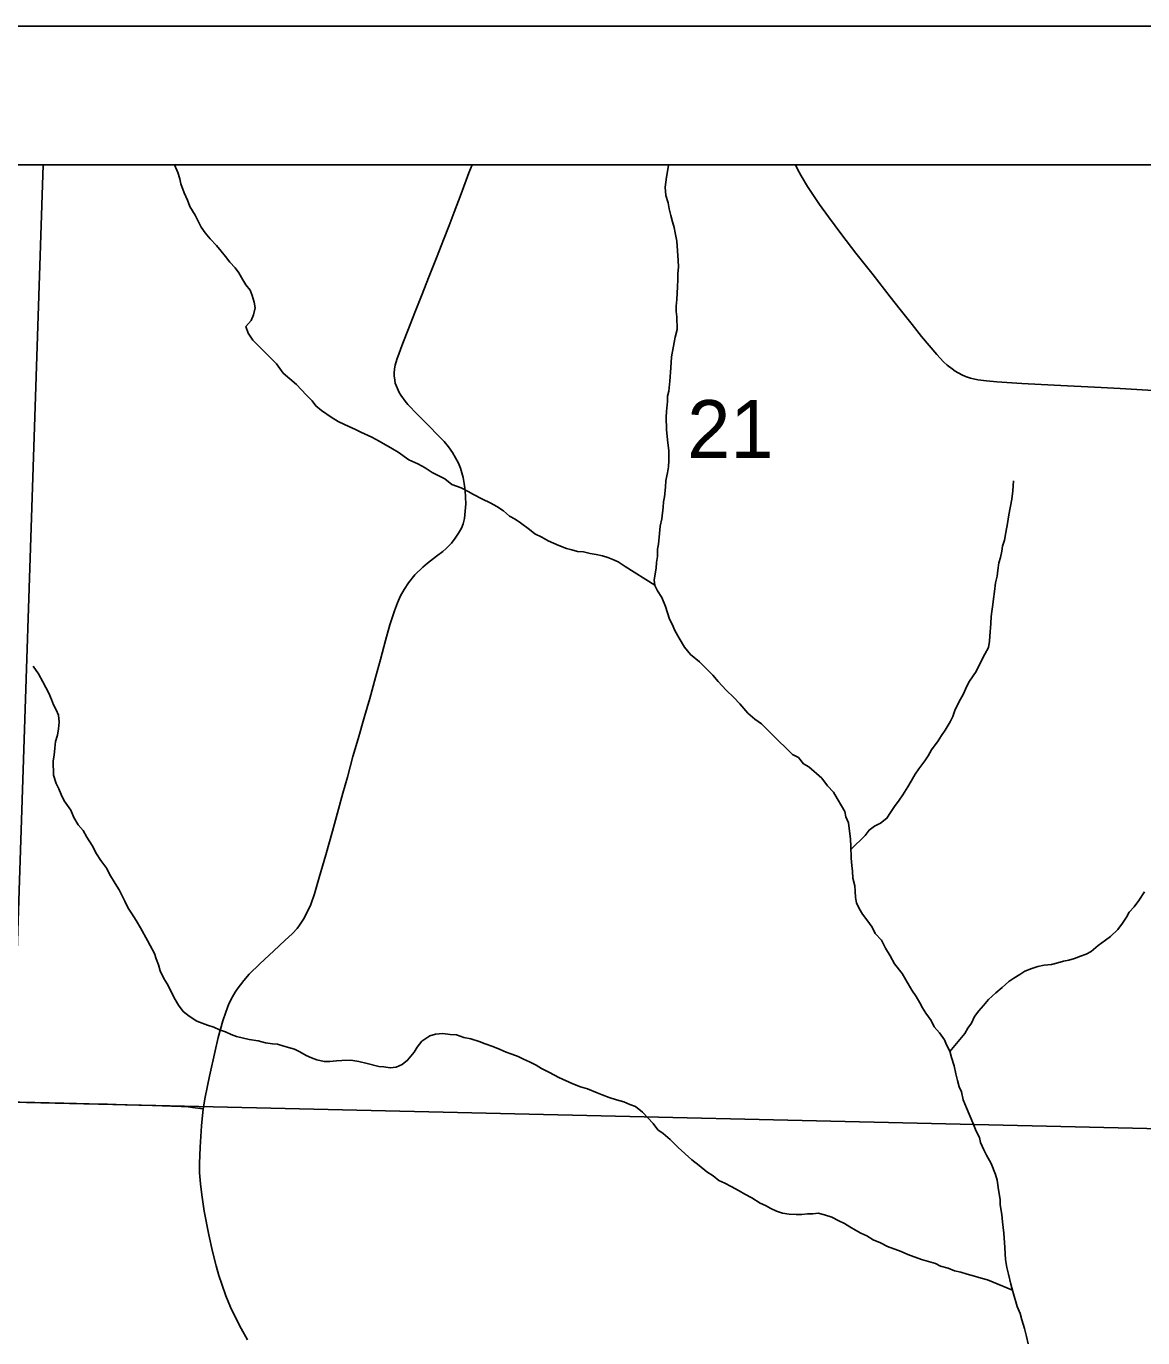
# Model space of a CAD drawing. Extents: x -7.9 to 76.1, y 0 to 22.
# Drawn here: x 7.388 to 8.194, y 20.053 to 21 of the extents above; entities that cross this region are included whole.
import ezdxf

# ---------------------------------------------------------------- set-up
doc = ezdxf.new("R2010")
doc.units = 0
for name, color, linetype in [('GM_X_County_Road', 7, 'Continuous'), ('GM_X_Minor_River', 7, 'Continuous'), ('GM_X_Section', 7, 'Continuous'), ('GM_X_Section_Text', 7, 'Continuous'), ('GM_X_Township_Road', 7, 'Continuous'), ('SC_Scratch1', 7, 'Continuous'), ('SH_Data', 7, 'Continuous')]:
    doc.layers.add(name, color=color, linetype=linetype)

msp = doc.modelspace()

# ---------------------------------------------------------------- linework, layer by layer
at = {"layer": 'GM_X_County_Road'}
for points in [[(7.54723, 20.05132), (7.54263, 20.05954), (7.53885, 20.06693), (7.53499, 20.07499), (7.53153, 20.08304), (7.52865, 20.09143), (7.5266, 20.09776), (7.52471, 20.10483), (7.522, 20.11511), (7.51928, 20.12719), (7.51592, 20.14437), (7.51419, 20.15596), (7.51329, 20.16402), (7.51271, 20.17191), (7.51263, 20.17865), (7.51312, 20.19049), (7.51411, 20.20578), (7.51526, 20.21819), (7.51666, 20.22649), (7.51986, 20.24178), (7.52397, 20.26011), (7.52619, 20.26956), (7.5294, 20.28165), (7.53153, 20.28789), (7.5339, 20.29391), (7.53655, 20.29908), (7.53844, 20.30241), (7.53975, 20.30446), (7.54462, 20.31089), (7.54847, 20.31543), (7.55619, 20.32299), (7.56619, 20.33218), (7.57428, 20.33961), (7.57987, 20.34486), (7.58307, 20.34847), (7.58488, 20.35078), (7.58776, 20.35522), (7.59039, 20.36023), (7.59294, 20.36582), (7.59573, 20.37339), (7.59915, 20.38522), (7.60378, 20.40161), (7.60861, 20.41869), (7.61229, 20.43192), (7.61621, 20.44605), (7.61938, 20.45759), (7.62346, 20.47267), (7.62731, 20.48545), (7.63188, 20.50158), (7.63555, 20.5145), (7.63969, 20.5297), (7.64324, 20.54274), (7.64696, 20.55643), (7.65003, 20.56768), (7.65344, 20.57782), (7.6555, 20.58358), (7.65779, 20.58859), (7.66035, 20.59328), (7.66347, 20.59812), (7.66809, 20.60383), (7.67393, 20.60929), (7.67728, 20.61227), (7.68385, 20.61719), (7.68844, 20.62077), (7.69078, 20.62283), (7.69456, 20.62677), (7.69716, 20.63027), (7.69974, 20.63383), (7.7018, 20.63747), (7.70297, 20.64061), (7.70401, 20.64456), (7.70457, 20.64983), (7.70488, 20.65507), (7.7045, 20.66459), (7.70375, 20.66988), (7.70297, 20.67417), (7.70109, 20.68093), (7.69964, 20.68452), (7.69759, 20.68835), (7.69528, 20.69217), (7.69232, 20.69627), (7.68936, 20.70006), (7.68517, 20.70425), (7.67799, 20.71154), (7.66996, 20.7197), (7.66306, 20.72691), (7.66112, 20.72926), (7.65808, 20.73345), (7.65691, 20.73543), (7.65525, 20.73877), (7.65399, 20.74213), (7.65356, 20.74441), (7.65325, 20.74754), (7.65322, 20.74933), (7.65344, 20.75256), (7.65389, 20.75511), (7.65501, 20.75923), (7.6594, 20.77114), (7.66344, 20.78136), (7.66813, 20.79322), (7.67289, 20.80526), (7.67854, 20.81939), (7.68386, 20.83272), (7.68885, 20.8457), (7.69281, 20.85599), (7.69658, 20.86578), (7.7015, 20.87897), (7.70717, 20.89418), (7.70946, 20.9)], [(8.2054, 20.73666), (8.17732, 20.73839), (8.16373, 20.73916), (8.1298, 20.74077), (8.10638, 20.74203), (8.08827, 20.74314), (8.08085, 20.74386), (8.07455, 20.7447), (8.06942, 20.74583), (8.06564, 20.74698), (8.06319, 20.7482), (8.05826, 20.751), (8.05611, 20.75251), (8.05257, 20.75528), (8.04993, 20.7576), (8.04503, 20.76293), (8.03408, 20.77595), (8.02725, 20.78468), (8.01869, 20.79539), (8.01127, 20.80467), (7.99904, 20.82041), (7.98659, 20.83616), (7.97636, 20.84945), (7.9668, 20.86242), (7.96036, 20.87114), (7.95165, 20.88424), (7.9471, 20.8919), (7.94448, 20.89673), (7.94298, 20.9)]]:
    msp.add_lwpolyline(points, dxfattribs=at)
at = {"layer": 'GM_X_Minor_River'}
for points in [[(7.4945, 20.9), (7.49688, 20.89444), (7.49845, 20.88991), (7.49926, 20.88612), (7.50162, 20.8797), (7.50397, 20.87442), (7.50555, 20.86989), (7.50943, 20.8635), (7.51137, 20.85973), (7.51371, 20.85483), (7.5168, 20.8507), (7.52027, 20.84657), (7.52488, 20.8417), (7.52835, 20.83758), (7.53144, 20.83382), (7.53452, 20.82969), (7.53837, 20.82557), (7.54108, 20.82181), (7.5438, 20.81692), (7.54612, 20.81316), (7.54921, 20.80941), (7.55077, 20.80563), (7.55198, 20.80072), (7.55279, 20.79655), (7.55172, 20.79161), (7.54988, 20.78741), (7.54615, 20.78318), (7.54773, 20.77827), (7.55121, 20.77339), (7.55467, 20.76964), (7.55889, 20.76553), (7.56274, 20.76178), (7.56812, 20.75617), (7.57314, 20.74941), (7.57775, 20.7453), (7.58273, 20.74119), (7.58966, 20.7337), (7.59388, 20.72958), (7.59659, 20.72583), (7.6008, 20.72247), (7.60769, 20.71763), (7.61266, 20.71466), (7.61724, 20.71245), (7.62525, 20.70877), (7.62907, 20.70692), (7.63708, 20.70324), (7.64243, 20.70028), (7.65198, 20.69472), (7.65618, 20.6925), (7.66384, 20.68691), (7.67033, 20.68397), (7.67568, 20.68101), (7.68065, 20.67766), (7.68981, 20.67323), (7.6948, 20.66913), (7.70165, 20.66657), (7.70662, 20.66398), (7.71044, 20.66176), (7.71655, 20.6588), (7.72304, 20.65548), (7.72724, 20.65326), (7.73221, 20.64992), (7.73643, 20.64618), (7.74063, 20.64396), (7.74446, 20.64136), (7.75097, 20.63652), (7.7548, 20.63353), (7.75977, 20.63095), (7.76435, 20.62835), (7.77198, 20.62504), (7.7777, 20.62285), (7.7815, 20.62176)], [(7.85139, 20.9), (7.85134, 20.89933), (7.84994, 20.89096), (7.8489, 20.88374), (7.84936, 20.87768), (7.85095, 20.87239), (7.85176, 20.86823), (7.85296, 20.86331), (7.85416, 20.85877), (7.85535, 20.85462), (7.85616, 20.85083), (7.85738, 20.84478), (7.85833, 20.83075), (7.85839, 20.8262), (7.85808, 20.82126), (7.85813, 20.81709), (7.85783, 20.81177), (7.85719, 20.80266), (7.85688, 20.79772), (7.85693, 20.79393), (7.85736, 20.79014), (7.85748, 20.78104), (7.85604, 20.77533), (7.85533, 20.77152), (7.85357, 20.76125), (7.85292, 20.75328), (7.85229, 20.74378), (7.85163, 20.73656), (7.85054, 20.73275), (7.85059, 20.72896), (7.84993, 20.72174), (7.84961, 20.71756), (7.84973, 20.70884), (7.85059, 20.70126), (7.85145, 20.69331), (7.85154, 20.68648), (7.85122, 20.68192), (7.85053, 20.67736), (7.84946, 20.67203), (7.84915, 20.66709), (7.84848, 20.66025), (7.84777, 20.65645), (7.84745, 20.65265), (7.84642, 20.64429), (7.84535, 20.63896), (7.84467, 20.63364), (7.84401, 20.62604), (7.8433, 20.62224), (7.84337, 20.61693), (7.84267, 20.61275), (7.84235, 20.60857), (7.84095, 20.6002), (7.84138, 20.59603), (7.84333, 20.59227), (7.84642, 20.58738), (7.84916, 20.58097), (7.85194, 20.5719), (7.85389, 20.56813), (7.85584, 20.5636), (7.85895, 20.55796), (7.86283, 20.55156)], [(8.10048, 20.67175), (8.09982, 20.66453), (8.09914, 20.65845), (8.09702, 20.64704), (8.09596, 20.64096), (8.09491, 20.63449), (8.09385, 20.62879), (8.09239, 20.62459), (8.09206, 20.62079), (8.09098, 20.61622), (8.0899, 20.61241), (8.08921, 20.60709), (8.08851, 20.60291), (8.08744, 20.59796), (8.08676, 20.59188), (8.08607, 20.58656), (8.08537, 20.58238), (8.08468, 20.57743), (8.08435, 20.57363), (8.08404, 20.5687), (8.0834, 20.55958), (8.08308, 20.55578), (8.08238, 20.55122), (8.07978, 20.54663), (8.07683, 20.5409), (8.07351, 20.53402), (8.06867, 20.52712), (8.06645, 20.52292), (8.06424, 20.51795), (8.06091, 20.51184), (8.05796, 20.50572), (8.0565, 20.50153), (8.05466, 20.49771), (8.05095, 20.49159), (8.04834, 20.48776), (8.04612, 20.48393), (8.04128, 20.47741), (8.03868, 20.4732), (8.03646, 20.46938), (8.03198, 20.46362), (8.02938, 20.45979), (8.02641, 20.45482), (8.0242, 20.45061), (8.02048, 20.44487), (8.01788, 20.44104), (8.01453, 20.43644), (8.01155, 20.43222), (8.00895, 20.42801), (8.00445, 20.42454), (7.99993, 20.42219), (7.99618, 20.41949), (7.99319, 20.41565), (7.98309, 20.40564)], [(7.7815, 20.62176), (7.78569, 20.62068), (7.78987, 20.62036), (7.79481, 20.61929), (7.79899, 20.61859), (7.80355, 20.61751), (7.80736, 20.61643), (7.81117, 20.61497), (7.81499, 20.61312), (7.81996, 20.60977), (7.84135, 20.59631)], [(7.86283, 20.55156), (7.86707, 20.54631), (7.87359, 20.54109), (7.87781, 20.53697), (7.8832, 20.53135), (7.88705, 20.52686), (7.89282, 20.52049), (7.89858, 20.51525), (7.90281, 20.51076), (7.90859, 20.50401), (7.91358, 20.49953), (7.91855, 20.49618), (7.92586, 20.48869), (7.94084, 20.47411), (7.94504, 20.47189), (7.94889, 20.46739), (7.95272, 20.46517), (7.96193, 20.45695), (7.96617, 20.45132), (7.97041, 20.44682), (7.97312, 20.44231), (7.97622, 20.43704), (7.97855, 20.4329), (7.97936, 20.42912), (7.98132, 20.42459), (7.98261, 20.41284), (7.98306, 20.40792), (7.98318, 20.39919), (7.98363, 20.39389), (7.98406, 20.38972), (7.98451, 20.3848), (7.98572, 20.37912), (7.98615, 20.37533), (7.98621, 20.37078), (7.98702, 20.367), (7.98897, 20.36285), (7.9913, 20.35871), (7.99439, 20.35458), (7.99825, 20.34932), (8.00059, 20.3448), (8.00521, 20.33993), (8.00794, 20.33428), (8.01143, 20.32864), (8.01453, 20.32299), (8.01994, 20.31586), (8.02265, 20.31134), (8.02692, 20.30381), (8.03002, 20.2993), (8.03273, 20.29479), (8.03468, 20.29102), (8.03701, 20.28726), (8.04087, 20.282), (8.0432, 20.27748), (8.04706, 20.27298), (8.05053, 20.2681), (8.0521, 20.26433), (8.05444, 20.25981), (8.05563, 20.25527), (8.05761, 20.24923), (8.05883, 20.24355), (8.06003, 20.23864), (8.06123, 20.2341), (8.0628, 20.23033), (8.06401, 20.22465), (8.06636, 20.21899), (8.07106, 20.20806), (8.07341, 20.20202), (8.07575, 20.1975), (8.07656, 20.19372), (8.0789, 20.18844), (8.08085, 20.18467), (8.08434, 20.17865), (8.08748, 20.17072), (8.08868, 20.16657), (8.08953, 20.15975), (8.09076, 20.15256), (8.09081, 20.14876), (8.09204, 20.14195), (8.09249, 20.13665), (8.09336, 20.12831), (8.09426, 20.11808), (8.09432, 20.11353), (8.09475, 20.10936), (8.09559, 20.10368), (8.09679, 20.09876), (8.09841, 20.09158), (8.09999, 20.08629), (8.10317, 20.07533), (8.10513, 20.07042), (8.10633, 20.06588), (8.10831, 20.05946), (8.10991, 20.0538), (8.11112, 20.0485)], [(7.39245, 20.53786), (7.39632, 20.53223), (7.39943, 20.52658), (7.40371, 20.51829), (7.40567, 20.51376), (7.40723, 20.50999), (7.40918, 20.50622), (7.41075, 20.50245), (7.4112, 20.49752), (7.41088, 20.49258), (7.41018, 20.48802), (7.40873, 20.48345), (7.40804, 20.47851), (7.40772, 20.47357), (7.40702, 20.46938), (7.40716, 20.45914), (7.40914, 20.4531), (7.41108, 20.44933), (7.41266, 20.44518), (7.41499, 20.44066), (7.41963, 20.43389), (7.42198, 20.42861), (7.42508, 20.42334), (7.42855, 20.41922), (7.43127, 20.41432), (7.43514, 20.4083), (7.43826, 20.40228), (7.44136, 20.39738), (7.4456, 20.39175), (7.44755, 20.38761), (7.45181, 20.38083), (7.45453, 20.37632), (7.45881, 20.36803), (7.46115, 20.36313), (7.46348, 20.35937), (7.46696, 20.3541), (7.47007, 20.34883), (7.47512, 20.3398), (7.47706, 20.33603), (7.48017, 20.33038), (7.48136, 20.3266), (7.48294, 20.32207), (7.48413, 20.31791), (7.48686, 20.31226), (7.48919, 20.3085), (7.49503, 20.29719), (7.49736, 20.29305), (7.50083, 20.28855), (7.50505, 20.28519), (7.51078, 20.28148), (7.51841, 20.27855), (7.52298, 20.27709), (7.52717, 20.27525), (7.53136, 20.27379), (7.53556, 20.27195), (7.53937, 20.27048), (7.5485, 20.26833), (7.55496, 20.26729), (7.56029, 20.26584), (7.56523, 20.26515), (7.56902, 20.26482), (7.57359, 20.26337), (7.5812, 20.2612), (7.58502, 20.25935), (7.58961, 20.25676), (7.59342, 20.25491), (7.59723, 20.25345), (7.60255, 20.25239), (7.60673, 20.25244), (7.61165, 20.25289), (7.61544, 20.25294), (7.62188, 20.25341), (7.62758, 20.25235), (7.63367, 20.25092), (7.64204, 20.24876), (7.64584, 20.24843), (7.6504, 20.24773), (7.65456, 20.24817), (7.65908, 20.25013), (7.66284, 20.25322), (7.66769, 20.25897), (7.66991, 20.2628), (7.67327, 20.26702), (7.6789, 20.27089), (7.68306, 20.27209), (7.68836, 20.27254), (7.69368, 20.27185), (7.69823, 20.27154), (7.70357, 20.26972), (7.70851, 20.26865), (7.7146, 20.26683), (7.7188, 20.26499), (7.72451, 20.26317), (7.72985, 20.26097), (7.73404, 20.25913), (7.73823, 20.25767), (7.74281, 20.25584), (7.74662, 20.25399), (7.75082, 20.25216), (7.75578, 20.24957), (7.7596, 20.24735)], [(8.19508, 20.37486), (8.19099, 20.36873), (8.18764, 20.36413), (8.1839, 20.36028), (8.18206, 20.35646), (8.17908, 20.35225), (8.17573, 20.34765), (8.17049, 20.34264), (8.16673, 20.33993), (8.16148, 20.33606), (8.1566, 20.33182), (8.15284, 20.32987), (8.14869, 20.32829), (8.14454, 20.32672), (8.14039, 20.32552), (8.13661, 20.32471), (8.13245, 20.32351), (8.12792, 20.32231), (8.12261, 20.32185), (8.11808, 20.32103), (8.11355, 20.31945), (8.10864, 20.31748), (8.10488, 20.31516), (8.10075, 20.31244), (8.09699, 20.31011), (8.09212, 20.30587), (8.08762, 20.30201), (8.08237, 20.297), (8.07864, 20.29278), (8.07528, 20.28894), (8.0723, 20.28472), (8.07009, 20.28013), (8.06749, 20.2763), (8.06526, 20.27248), (8.05448, 20.25963)], [(7.7596, 20.24735), (7.76533, 20.24439), (7.77221, 20.24069), (7.78212, 20.23628), (7.78784, 20.23408), (7.79279, 20.23263), (7.79966, 20.22969), (7.80347, 20.22822), (7.80842, 20.22639), (7.81375, 20.22457), (7.81908, 20.22313), (7.82328, 20.22129), (7.82747, 20.21983), (7.83245, 20.21573), (7.84015, 20.20748), (7.84362, 20.20298), (7.84745, 20.20038), (7.85244, 20.19589), (7.8582, 20.19028), (7.86818, 20.18131), (7.87354, 20.17722), (7.87891, 20.17274), (7.8835, 20.16976), (7.88771, 20.16641), (7.89191, 20.16457), (7.8965, 20.16198), (7.90222, 20.15902), (7.90643, 20.15643), (7.91139, 20.15384), (7.91751, 20.15013), (7.92133, 20.14829), (7.92515, 20.14606), (7.92934, 20.14422), (7.93353, 20.14276), (7.93847, 20.14208), (7.94341, 20.14176), (7.94758, 20.14182), (7.95174, 20.14226), (7.95553, 20.14231), (7.95932, 20.14275), (7.96388, 20.14167), (7.96922, 20.13985), (7.97418, 20.13726), (7.97837, 20.13542), (7.9822, 20.13282), (7.9864, 20.1306), (7.99022, 20.12838), (7.99442, 20.12654), (7.99901, 20.12357), (8.00435, 20.12137), (8.00931, 20.11878), (8.01922, 20.11513), (8.02418, 20.11292), (8.03409, 20.10926), (8.04398, 20.10637), (8.0478, 20.10452), (8.05313, 20.10308), (8.0577, 20.10125), (8.06227, 20.10017), (8.06684, 20.09872), (8.07216, 20.09728), (8.07711, 20.09583), (8.08168, 20.09476), (8.09969, 20.08729)]]:
    msp.add_lwpolyline(points, dxfattribs=at)
at = {"layer": 'GM_X_Section'}
msp.add_lwpolyline([(7.37741, 20.22298), (8.39386, 20.19938), (8.3601, 19.17786), (7.34206, 19.2056)], close=True, dxfattribs=at)
at = {"layer": 'GM_X_Township_Road'}
msp.add_lwpolyline([(7.51526, 20.21819), (7.50762, 20.21917), (7.50438, 20.21956), (7.49948, 20.21986), (7.47873, 20.22052), (7.45899, 20.22116), (7.44609, 20.22146), (7.43288, 20.22177), (7.41469, 20.22221), (7.39361, 20.22273), (7.38278, 20.223), (7.37737, 20.22336), (7.37265, 20.22384), (7.36484, 20.22501), (7.35714, 20.22571), (7.35202, 20.22595), (7.3474, 20.22587), (7.34318, 20.22558), (7.33624, 20.22531)], dxfattribs=at)
at = {"layer": 'SC_Scratch1'}
for points in [[(7.39969, 20.9), (6.37773, 20.9), (6.35894, 20.25374), (7.37741, 20.22298)], [(8.4183, 20.9), (7.39969, 20.9), (7.37741, 20.22298), (8.39386, 20.19938)]]:
    msp.add_lwpolyline(points, close=True, dxfattribs=at)
at = {"layer": 'SH_Data'}
for p, q in [((2, 21), (9, 21)), ((2.1, 20.9), (8.9, 20.9))]:
    msp.add_line(p, q, dxfattribs=at)

# ---------------------------------------------------------------- texts
at = {"layer": 'GM_X_Section_Text'}
msp.add_text('21', height=0.041856, rotation=0.00001, dxfattribs=at).set_placement((7.86482, 20.68811))

doc.saveas('drawing.dxf')
